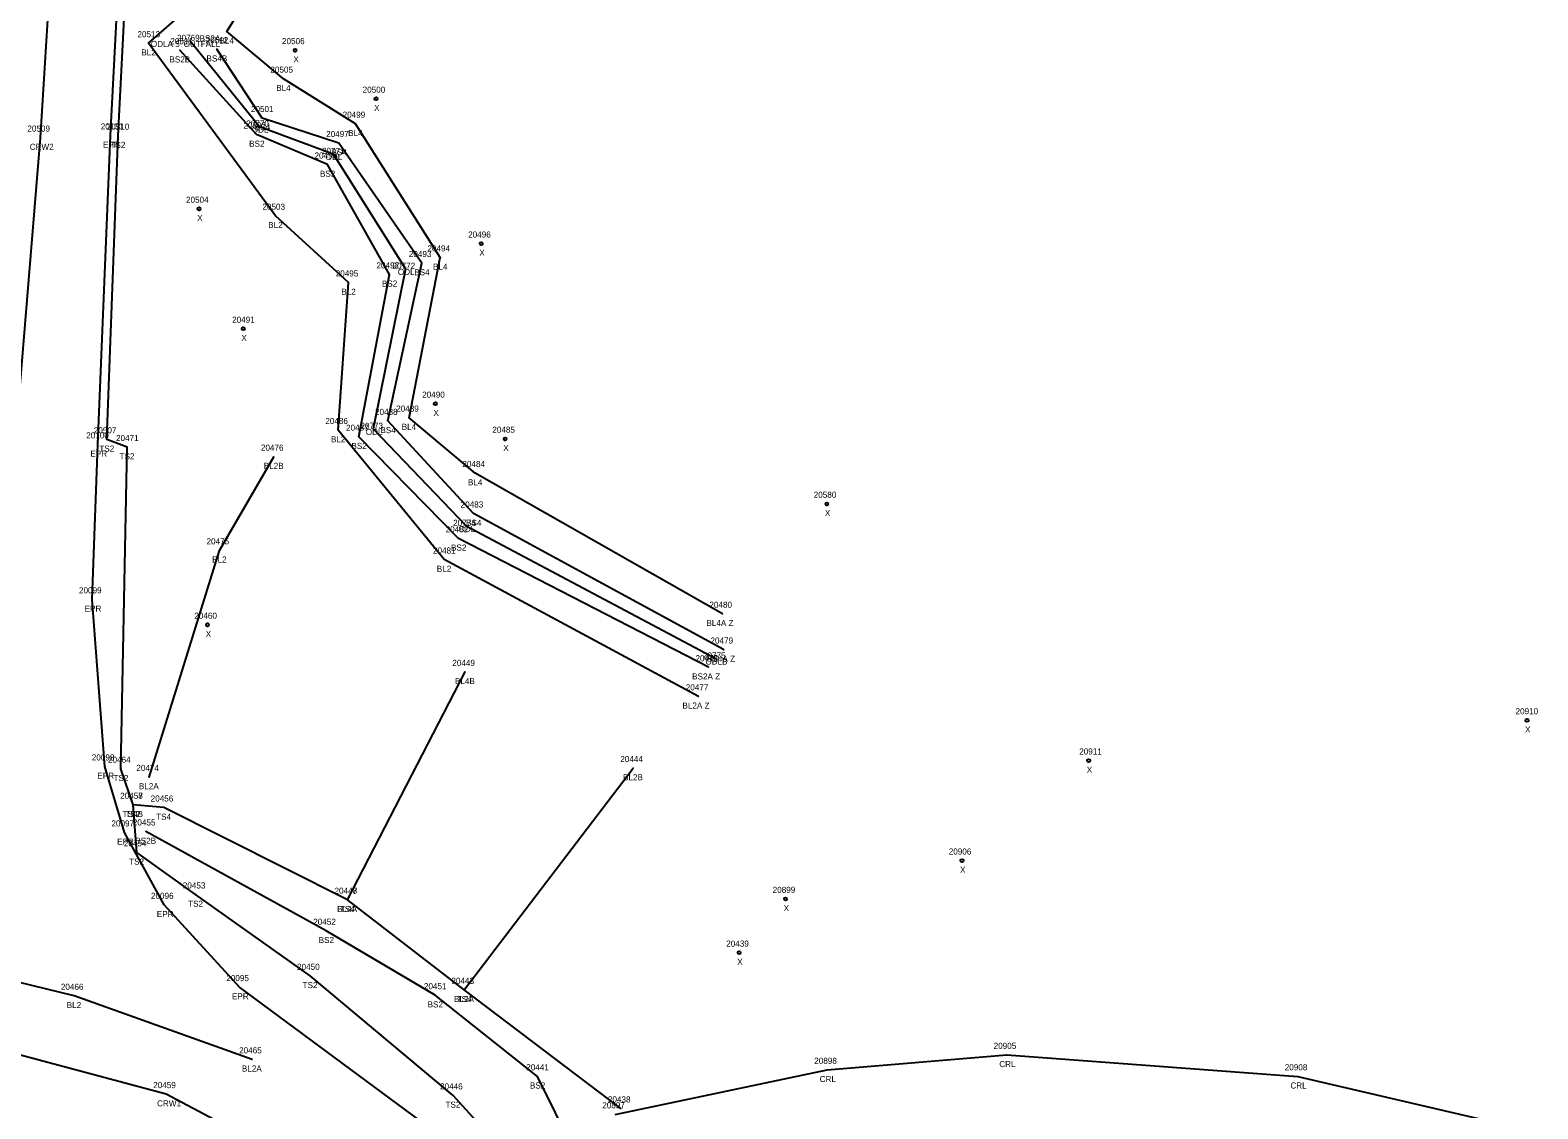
# Model space of a CAD drawing. Extents: x 1813127 to 1814107, y 1178171 to 1179078.
# Drawn here: x 1813671.6 to 1813919.6, y 1178740.3 to 1178917.6 of the extents above; entities that cross this region are included whole.
import ezdxf

# ---------------------------------------------------------------- set-up
doc = ezdxf.new("R2010")
doc.units = 0
for name, color, linetype in [('RD_DTM_BkLn1', 7, 'Continuous'), ('RD_DTM_BkLn2', 7, 'Continuous'), ('RD_EX_H2O', 7, 'Continuous'), ('RD_EX_H2O_txCode', 7, 'Continuous'), ('RD_EX_Road', 7, 'Continuous'), ('RD_EX_Road_txCode', 7, 'Continuous'), ('RD_SMD_Locator', 7, 'Continuous'), ('RD_SMD_Misc', 7, 'Continuous')]:
    doc.layers.add(name, color=color, linetype=linetype)

msp = doc.modelspace()

# ---------------------------------------------------------------- linework, layer by layer
at = {"layer": 'RD_DTM_BkLn1'}
for p, q in [((1813723.8, 1178774.61), (1813743.17, 1178812.08)), ((1813743.02, 1178759.81), (1813770.8, 1178796.27))]:
    msp.add_line(p, q, dxfattribs=at)
for points in [[(1813652.18, 1178753.85), (1813654.73, 1178764.67), (1813662.67, 1178799.96), (1813669.51, 1178850.38), (1813669.19, 1178849.87), (1813673.32, 1178899.93), (1813676.21, 1178946.85), (1813678.62, 1178996.65), (1813680.77, 1179045.99)], [(1813781.56, 1178808.06), (1813739.7, 1178830.55), (1813722.3, 1178851.85), (1813723.99, 1178876.11), (1813711.97, 1178887.08), (1813691.11, 1178915.45), (1813696.21, 1178919.94), (1813693.36, 1178948.36), (1813696.93, 1178995.1), (1813702.43, 1179045.97)], [(1813785.49, 1178821.63), (1813744.83, 1178844.78), (1813733.94, 1178853.89), (1813739.08, 1178880.23), (1813725.13, 1178902.21), (1813713.29, 1178909.62), (1813703.94, 1178917.4), (1813725.9, 1178952.77), (1813719.6, 1178998.9)], [(1813740.76, 1178717.86), (1813693.97, 1178742.65), (1813652.18, 1178753.85), (1813643.74, 1178755.64), (1813595, 1178763.51), (1813546.44, 1178770.61), (1813497.6, 1178777.62), (1813448.59, 1178785.89), (1813401.09, 1178795.04), (1813353.48, 1178806.76), (1813306.05, 1178819.85), (1813260.03, 1178834.12), (1813213.64, 1178849.47), (1813166.61, 1178866.29)], [(1813691.19, 1178794.81), (1813702.75, 1178832.07), (1813711.71, 1178847.47)], [(1813708.13, 1178748.38), (1813678.84, 1178758.82), (1813655.66, 1178764.45)]]:
    msp.add_lwpolyline(points, dxfattribs=at)
at = {"layer": 'RD_DTM_BkLn2'}
for points in [[(1813751.85, 1178730.74), (1813741.17, 1178742.44), (1813717.67, 1178762.1), (1813698.84, 1178775.48), (1813689.15, 1178782.4), (1813688.55, 1178790.23), (1813686.56, 1178796.15), (1813687.57, 1178849.05), (1813684.25, 1178850.31), (1813686.08, 1178900.25), (1813688.49, 1178947.42), (1813691.04, 1178995.37), (1813694.64, 1179045.56)], [(1813783.17, 1178812.85), (1813742.06, 1178834.04), (1813725.69, 1178850.75), (1813730.7, 1178877.44), (1813720.5, 1178895.5), (1813708.86, 1178900.44), (1813696.22, 1178914.3)], [(1813785.63, 1178815.75), (1813744.54, 1178838.12), (1813730.45, 1178853.35), (1813736.02, 1178879.31), (1813722.41, 1178899.04), (1813709.8, 1178903.15), (1813702.32, 1178914.46)], [(1813768.76, 1178740.3), (1813743.02, 1178759.81), (1813723.8, 1178774.61), (1813693.59, 1178789.78), (1813688.55, 1178790.23)], [(1813761, 1178733.6), (1813755.04, 1178745.59), (1813738.22, 1178758.92), (1813720.3, 1178769.51), (1813690.62, 1178785.84)]]:
    msp.add_lwpolyline(points, dxfattribs=at)
at = {"layer": 'RD_EX_H2O'}
for points in [[(1813697.92, 1178915.85), (1813709.32, 1178901.76), (1813721.45, 1178897.26), (1813733.34, 1178878.37), (1813728.06, 1178852.05), (1813743.31, 1178836.1), (1813784.4, 1178814.3)], [(1813767.83, 1178739.34), (1813802.7, 1178746.65), (1813832.24, 1178749.11), (1813880.12, 1178745.59), (1813913.04, 1178737.89)]]:
    msp.add_lwpolyline(points, dxfattribs=at)
at = {"layer": 'RD_EX_Road'}
msp.add_lwpolyline([(1813750.48, 1178727.17), (1813739.94, 1178735.23), (1813706.04, 1178760.25), (1813693.68, 1178773.78), (1813687.15, 1178785.68), (1813683.91, 1178796.53), (1813681.81, 1178824.01), (1813682.76, 1178849.48), (1813684.82, 1178900.28), (1813687.23, 1178946.66), (1813689.58, 1178995.92), (1813691.79, 1179045.45)], dxfattribs=at)
at = {"layer": 'RD_SMD_Locator'}
for centre, radius in [((1813703.94, 1178917.4), 0.001), ((1813691.11, 1178915.45), 0.001), ((1813697.92, 1178915.85), 0.001), ((1813715.22, 1178914.31), 0.25), ((1813696.22, 1178914.3), 0.001), ((1813702.32, 1178914.46), 0.001), ((1813713.29, 1178909.62), 0.001), ((1813728.5, 1178906.33), 0.25), ((1813709.8, 1178903.15), 0.001), ((1813725.13, 1178902.21), 0.001), ((1813673.32, 1178899.93), 0.001), ((1813684.82, 1178900.28), 0.001), ((1813686.08, 1178900.25), 0.001), ((1813708.86, 1178900.44), 0.001), ((1813709.32, 1178901.76), 0.001), ((1813721.45, 1178897.26), 0.001), ((1813722.41, 1178899.04), 0.001), ((1813720.5, 1178895.5), 0.001), ((1813699.4, 1178888.23), 0.25), ((1813711.97, 1178887.08), 0.001), ((1813745.8, 1178882.51), 0.25), ((1813739.08, 1178880.23), 0.001), ((1813730.7, 1178877.44), 0.001), ((1813733.34, 1178878.37), 0.001), ((1813736.02, 1178879.31), 0.001), ((1813723.99, 1178876.11), 0.001), ((1813706.67, 1178868.51), 0.25), ((1813738.26, 1178856.18), 0.25), ((1813730.45, 1178853.35), 0.001), ((1813733.94, 1178853.89), 0.001), ((1813684.25, 1178850.31), 0.001), ((1813722.3, 1178851.85), 0.001), ((1813725.69, 1178850.75), 0.001), ((1813728.06, 1178852.05), 0.001), ((1813749.75, 1178850.41), 0.25), ((1813682.76, 1178849.48), 0.001), ((1813687.57, 1178849.05), 0.001), ((1813711.71, 1178847.47), 0.001), ((1813744.83, 1178844.78), 0.001), ((1813744.54, 1178838.12), 0.001), ((1813802.65, 1178839.72), 0.25), ((1813743.31, 1178836.1), 0.001), ((1813742.06, 1178834.04), 0.001), ((1813702.75, 1178832.07), 0.001), ((1813739.7, 1178830.55), 0.001), ((1813681.81, 1178824.01), 0.001), ((1813785.49, 1178821.63), 0.001), ((1813700.8, 1178819.83), 0.25), ((1813785.63, 1178815.75), 0.001), ((1813784.4, 1178814.3), 0.001), ((1813743.17, 1178812.08), 0.001), ((1813783.17, 1178812.85), 0.001), ((1813781.56, 1178808.06), 0.001), ((1813917.79, 1178804.13), 0.25), ((1813683.91, 1178796.53), 0.001), ((1813686.56, 1178796.15), 0.001), ((1813770.8, 1178796.27), 0.001), ((1813845.71, 1178797.51), 0.25), ((1813691.19, 1178794.81), 0.001), ((1813688.55, 1178790.23), 0.001), ((1813688.55, 1178790.23), 0.001), ((1813693.59, 1178789.78), 0.001), ((1813687.15, 1178785.68), 0.001), ((1813690.62, 1178785.84), 0.001), ((1813689.15, 1178782.4), 0.001), ((1813824.88, 1178781.06), 0.25), ((1813693.68, 1178773.78), 0.001), ((1813698.84, 1178775.48), 0.001), ((1813723.8, 1178774.61), 0.001), ((1813723.8, 1178774.61), 0.001), ((1813795.86, 1178774.76), 0.25), ((1813720.3, 1178769.51), 0.001), ((1813788.22, 1178765.92), 0.25), ((1813717.67, 1178762.1), 0.001), ((1813678.84, 1178758.82), 0.001), ((1813706.04, 1178760.25), 0.001), ((1813738.22, 1178758.92), 0.001), ((1813743.02, 1178759.81), 0.001), ((1813743.02, 1178759.81), 0.001), ((1813832.24, 1178749.11), 0.001), ((1813708.13, 1178748.38), 0.001), ((1813802.7, 1178746.65), 0.001), ((1813755.04, 1178745.59), 0.001), ((1813880.12, 1178745.59), 0.001), ((1813693.97, 1178742.65), 0.001), ((1813741.17, 1178742.44), 0.001), ((1813768.76, 1178740.3), 0.001)]:
    msp.add_circle(centre, radius, dxfattribs=at)

# ---------------------------------------------------------------- texts
at = {"layer": 'RD_EX_H2O_txCode'}
for s, p in [("ODLA 5' OUTFALL", (1813691.47, 1178914.85)), ('20769', (1813695.78, 1178915.85)), ('20770', (1813707.16, 1178901.76)), ('ODL', (1813708.07, 1178900.76)), ('20771', (1813719.62, 1178897.26)), ('ODL', (1813720.21, 1178896.26)), ('20772', (1813731.22, 1178878.37)), ('ODL', (1813732.1, 1178877.37)), ('20773', (1813725.94, 1178852.05)), ('ODL', (1813726.82, 1178851.05)), ('20774', (1813741.19, 1178836.1)), ('ODL', (1813742.07, 1178835.1)), ('20775', (1813782.28, 1178814.3)), ('ODLB', (1813782.68, 1178813.3)), ('20905', (1813830.08, 1178750.11)), ('20898', (1813800.58, 1178747.65)), ('CRL', (1813831.01, 1178747.11)), ('20908', (1813877.96, 1178746.59)), ('CRL', (1813801.47, 1178744.65)), ('CRL', (1813878.89, 1178743.59)), ('20897', (1813765.71, 1178740.34))]:
    msp.add_text(s, height=1, dxfattribs=at).set_placement(p)
at = {"layer": 'RD_EX_Road_txCode'}
for s, p in [('20101', (1813683.23, 1178901.28)), ('EPR', (1813683.59, 1178898.28)), ('20100', (1813680.84, 1178850.48)), ('EPR', (1813681.53, 1178847.48)), ('20099', (1813679.65, 1178825.01)), ('EPR', (1813680.58, 1178822.01)), ('20098', (1813681.76, 1178797.53)), ('EPR', (1813682.68, 1178794.53)), ('20097', (1813684.99, 1178786.68)), ('EPR', (1813685.92, 1178783.68)), ('20096', (1813691.49, 1178774.78)), ('EPR', (1813692.45, 1178771.78)), ('20095', (1813703.88, 1178761.25)), ('EPR', (1813704.81, 1178758.25))]:
    msp.add_text(s, height=1, dxfattribs=at).set_placement(p)
at = {"layer": 'RD_SMD_Misc'}
for s, p in [('20513', (1813689.27, 1178916.45)), ('20511', (1813694.67, 1178915.3)), ('BS2A', (1813699.49, 1178915.76)), ('20512', (1813700.48, 1178915.46)), ('BL4', (1813702.74, 1178915.4)), ('20506', (1813713.04, 1178915.31)), ('BL2', (1813689.9, 1178913.45)), ('BS2B', (1813694.52, 1178912.3)), ('BS4B', (1813700.62, 1178912.46)), ('X', (1813714.91, 1178912.31)), ('20505', (1813711.13, 1178910.62)), ('BL4', (1813712.09, 1178907.62)), ('20500', (1813726.3, 1178907.33)), ('20501', (1813707.93, 1178904.15)), ('X', (1813728.19, 1178904.33)), ('20510', (1813684.2, 1178901.25)), ('20502', (1813706.7, 1178901.44)), ('BS4', (1813708.57, 1178901.15)), ('20499', (1813723.01, 1178903.21)), ('20509', (1813671.16, 1178900.93)), ('20497', (1813720.3, 1178900.04)), ('BL4', (1813723.92, 1178900.21)), ('CRW2', (1813671.55, 1178897.93)), ('TS2', (1813684.83, 1178898.25)), ('BS2', (1813707.63, 1178898.44)), ('20498', (1813718.39, 1178896.5)), ('BS4', (1813721.19, 1178897.04)), ('BS2', (1813719.28, 1178893.5)), ('20504', (1813697.25, 1178889.23)), ('20503', (1813709.82, 1178888.08)), ('X', (1813699.09, 1178886.23)), ('BL2', (1813710.77, 1178885.08)), ('20496', (1813743.66, 1178883.51)), ('20493', (1813733.9, 1178880.31)), ('20494', (1813736.96, 1178881.23)), ('X', (1813745.49, 1178880.51)), ('20495', (1813721.88, 1178877.11)), ('20492', (1813728.58, 1178878.44)), ('BS4', (1813734.79, 1178877.31)), ('BL4', (1813737.88, 1178878.23)), ('BL2', (1813722.79, 1178874.11)), ('BS2', (1813729.47, 1178875.44)), ('20491', (1813704.84, 1178869.51)), ('X', (1813706.36, 1178866.51)), ('20490', (1813736.1, 1178857.18)), ('20488', (1813728.33, 1178854.35)), ('20489', (1813731.82, 1178854.89)), ('X', (1813737.95, 1178854.18)), ('20486', (1813720.16, 1178852.85)), ('20487', (1813723.57, 1178851.75)), ('BL4', (1813732.73, 1178851.89)), ('20507', (1813682.09, 1178851.31)), ('20471', (1813685.74, 1178850.05)), ('BL2', (1813721.09, 1178849.85)), ('BS4', (1813729.22, 1178851.35)), ('20485', (1813747.63, 1178851.41)), ('TS2', (1813683, 1178848.31)), ('TS2', (1813686.33, 1178847.05)), ('20476', (1813709.57, 1178848.47)), ('BS2', (1813724.46, 1178848.75)), ('X', (1813749.43, 1178848.41)), ('BL2B', (1813710.04, 1178845.47)), ('20484', (1813742.71, 1178845.78)), ('BL4', (1813743.62, 1178842.78)), ('20580', (1813800.49, 1178840.72)), ('20483', (1813742.42, 1178839.12)), ('X', (1813802.33, 1178837.72)), ('20482', (1813739.95, 1178835.04)), ('BS4', (1813743.31, 1178836.12)), ('20475', (1813700.63, 1178833.07)), ('BS2', (1813740.84, 1178832.04)), ('BL2', (1813701.55, 1178830.07)), ('20481', (1813737.87, 1178831.55)), ('BL2', (1813738.5, 1178828.55)), ('20480', (1813783.33, 1178822.63)), ('20460', (1813698.62, 1178820.83)), ('BL4A Z', (1813782.84, 1178819.63)), ('X', (1813700.49, 1178817.83)), ('20479', (1813783.51, 1178816.75)), ('20449', (1813741.05, 1178813.08)), ('20478', (1813781.05, 1178813.85)), ('BS4A Z', (1813782.95, 1178813.75)), ('BL4B', (1813741.49, 1178810.08)), ('BS2A Z', (1813780.49, 1178810.85)), ('20477', (1813779.44, 1178809.06)), ('BL2A Z', (1813778.9, 1178806.06)), ('20910', (1813915.92, 1178805.13)), ('X', (1813917.48, 1178802.13)), ('20464', (1813684.42, 1178797.15)), ('20444', (1813768.68, 1178797.27)), ('20911', (1813844.16, 1178798.51)), ('20474', (1813689.08, 1178795.81)), ('X', (1813845.4, 1178795.51)), ('TS2', (1813685.32, 1178794.15)), ('BL2A', (1813689.5, 1178792.81)), ('BL2B', (1813769.13, 1178794.27)), ('20457', (1813686.43, 1178791.23)), ('20458', (1813686.43, 1178791.23)), ('20456', (1813691.44, 1178790.78)), ('TS4B', (1813686.83, 1178788.23)), ('TS2', (1813687.3, 1178788.23)), ('TS4', (1813692.34, 1178787.78)), ('20455', (1813688.51, 1178786.84)), ('20454', (1813687.03, 1178783.4)), ('BS2B', (1813688.92, 1178783.84)), ('TS2', (1813687.9, 1178780.4)), ('20906', (1813822.7, 1178782.06)), ('X', (1813824.56, 1178779.06)), ('20453', (1813696.73, 1178776.48)), ('20447', (1813721.68, 1178775.61)), ('20448', (1813721.68, 1178775.61)), ('20899', (1813793.74, 1178775.76)), ('TS2', (1813697.6, 1178773.48)), ('BL4A', (1813722.1, 1178772.61)), ('TS4', (1813722.55, 1178772.61)), ('X', (1813795.55, 1178772.76)), ('20452', (1813718.18, 1178770.51)), ('BS2', (1813719.07, 1178767.51)), ('20439', (1813786.1, 1178766.92)), ('20450', (1813715.52, 1178763.1)), ('X', (1813787.91, 1178763.92)), ('20466', (1813676.67, 1178759.82)), ('TS2', (1813716.43, 1178760.1)), ('20451', (1813736.38, 1178759.92)), ('20442', (1813740.9, 1178760.81)), ('20443', (1813740.9, 1178760.81)), ('BL2A', (1813741.33, 1178757.81)), ('TS4', (1813741.78, 1178757.81)), ('BL2', (1813677.63, 1178756.82)), ('BS2', (1813736.99, 1178756.92)), ('20465', (1813705.99, 1178749.38)), ('BL2A', (1813706.44, 1178746.38)), ('20441', (1813753.21, 1178746.59)), ('20459', (1813691.86, 1178743.65)), ('20446', (1813739.03, 1178743.44)), ('BS2', (1813753.81, 1178743.59)), ('CRW1', (1813692.49, 1178740.65)), ('TS2', (1813739.93, 1178740.44)), ('20438', (1813766.64, 1178741.3))]:
    msp.add_text(s, height=1, dxfattribs=at).set_placement(p)

doc.saveas('drawing.dxf')
